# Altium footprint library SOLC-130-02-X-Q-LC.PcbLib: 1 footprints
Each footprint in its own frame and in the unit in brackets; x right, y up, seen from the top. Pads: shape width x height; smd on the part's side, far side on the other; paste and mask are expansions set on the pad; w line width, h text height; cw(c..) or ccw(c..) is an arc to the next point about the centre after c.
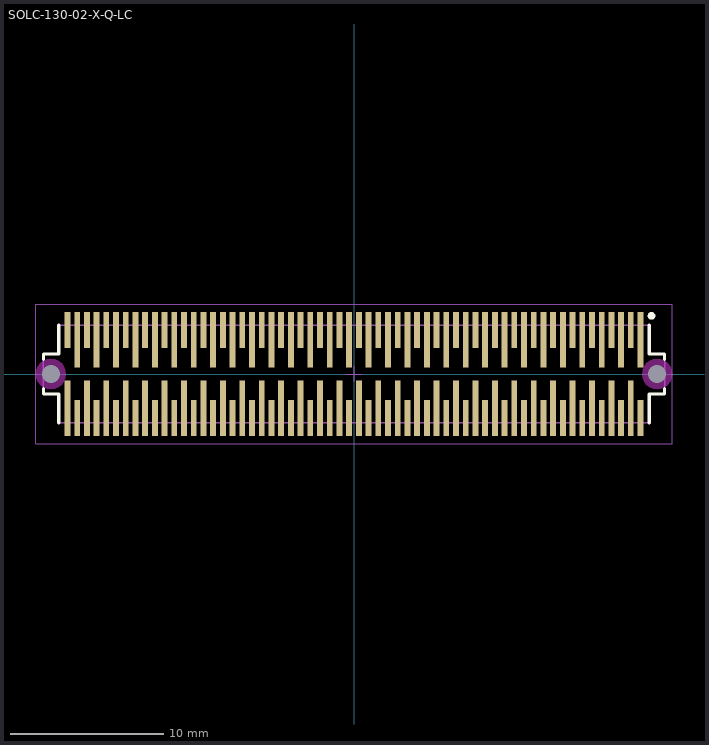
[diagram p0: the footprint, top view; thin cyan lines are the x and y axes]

## SOLC-130-02-X-Q-LC [mm] "1.27mm pitch, 120 pin, socket strip; 4 rows, w/locking clips, SMT"
height 4.62
pads (122):
  rect 0.38x2.36 smd mask+0: A1(18.098,2.885) A2(16.828,2.885) A3(15.557,2.885) A4(14.287,2.885) A5(13.018,2.885) A6(11.747,2.885) A7(10.477,2.885) A8(9.207,2.885) A9(7.938,2.885) A10(6.667,2.885) A11(5.397,2.885) A12(4.127,2.885) A13(2.857,2.885) A14(1.587,2.885) A15(0.318,2.885) A16(-0.953,2.885) A17(-2.222,2.885) A18(-3.492,2.885) A19(-4.763,2.885) A20(-6.032,2.885) A21(-7.302,2.885) A22(-8.572,2.885) A23(-9.842,2.885) A24(-11.112,2.885) A25(-12.383,2.885) A26(-13.652,2.885) A27(-14.922,2.885) A28(-16.192,2.885) A29(-17.462,2.885) A30(-18.732,2.885) D1(18.732,-2.885) D2(17.462,-2.885) D3(16.192,-2.885) D4(14.922,-2.885) D5(13.652,-2.885) D6(12.383,-2.885) D7(11.112,-2.885) D8(9.842,-2.885) D9(8.572,-2.885) D10(7.302,-2.885) D11(6.032,-2.885) D12(4.763,-2.885) D13(3.492,-2.885) D14(2.222,-2.885) D15(0.953,-2.885) D16(-0.318,-2.885) D17(-1.587,-2.885) D18(-2.857,-2.885) D19(-4.127,-2.885) D20(-5.397,-2.885) D21(-6.667,-2.885) D22(-7.938,-2.885) D23(-9.207,-2.885) D24(-10.477,-2.885) D25(-11.747,-2.885) D26(-13.018,-2.885) D27(-14.287,-2.885) D28(-15.557,-2.885) D29(-16.828,-2.885) D30(-18.098,-2.885)
  rect 0.38x3.63 smd mask+0: B1(18.732,2.25) B2(17.462,2.25) B3(16.192,2.25) B4(14.922,2.25) B5(13.652,2.25) B6(12.383,2.25) B7(11.112,2.25) B8(9.842,2.25) B9(8.572,2.25) B10(7.302,2.25) B11(6.032,2.25) B12(4.763,2.25) B13(3.492,2.25) B14(2.222,2.25) B15(0.953,2.25) B16(-0.318,2.25) B17(-1.587,2.25) B18(-2.857,2.25) B19(-4.127,2.25) B20(-5.397,2.25) B21(-6.667,2.25) B22(-7.938,2.25) B23(-9.207,2.25) B24(-10.477,2.25) B25(-11.747,2.25) B26(-13.018,2.25) B27(-14.287,2.25) B28(-15.557,2.25) B29(-16.828,2.25) B30(-18.098,2.25) C1(18.098,-2.25) C2(16.828,-2.25) C3(15.557,-2.25) C4(14.287,-2.25) C5(13.018,-2.25) C6(11.747,-2.25) C7(10.477,-2.25) C8(9.207,-2.25) C9(7.938,-2.25) C10(6.667,-2.25) C11(5.397,-2.25) C12(4.127,-2.25) C13(2.857,-2.25) C14(1.587,-2.25) C15(0.318,-2.25) C16(-0.953,-2.25) C17(-2.222,-2.25) C18(-3.492,-2.25) C19(-4.763,-2.25) C20(-6.032,-2.25) C21(-7.302,-2.25) C22(-8.572,-2.25) C23(-9.842,-2.25) C24(-11.112,-2.25) C25(-12.383,-2.25) C26(-13.652,-2.25) C27(-14.922,-2.25) C28(-16.192,-2.25) C29(-17.462,-2.25) C30(-18.732,-2.25)
  round 1 hole 1.2 unplated mask+0: MTG1(-19.812,0) MTG2(19.812,0)
Top Overlay:
  circle w0.25: c19.45,3.8 r0.125
  lines w0.2: -20.3,-0.95 -20.3,-1.3 -19.3,-1.3 -19.3,-3.2 ; -20.3,0.95 -20.3,1.3 -19.3,1.3 -19.3,3.2 ; 19.3,-3.2 19.3,-1.3 20.3,-1.3 20.3,-0.95 ; 19.3,3.2 19.3,1.3 20.3,1.3 20.3,0.95
Keep-Out Layer:
  pour cut-out: 20.795,0 20.762,0.255 20.664,0.492 20.507,0.695 20.304,0.852 20.067,0.95 19.812,0.983 19.557,0.95 19.32,0.852 19.117,0.695 18.96,0.492 18.862,0.255 18.829,0 18.862,-0.255 18.96,-0.492 19.117,-0.695 19.32,-0.852 19.557,-0.95 19.812,-0.983 20.067,-0.95 20.304,-0.852 20.507,-0.695 20.664,-0.492 20.762,-0.255
  pour cut-out: -18.829,0 -18.862,0.255 -18.96,0.492 -19.117,0.695 -19.32,0.852 -19.557,0.95 -19.812,0.983 -20.067,0.95 -20.304,0.852 -20.507,0.695 -20.664,0.492 -20.762,0.255 -20.795,0 -20.762,-0.255 -20.664,-0.492 -20.507,-0.695 -20.304,-0.852 -20.067,-0.95 -19.812,-0.983 -19.557,-0.95 -19.32,-0.852 -19.117,-0.695 -18.96,-0.492 -18.862,-0.255
Mechanical 12:
  lines w0.001: -20.3,-1.3 -20.3,1.3 -19.3,1.3 -19.3,3.2 19.3,3.2 19.3,1.3 20.3,1.3 20.3,-1.3 19.3,-1.3 19.3,-3.2 -19.3,-3.2 -19.3,-1.3 -20.3,-1.3
Mechanical 13:
  lines w0.1: -20.3,-1.3 -20.3,1.3 -19.3,1.3 -19.3,3.2 19.3,3.2 19.3,1.3 20.3,1.3 20.3,-1.3 19.3,-1.3 19.3,-3.2 -19.3,-3.2 -19.3,-1.3 -20.3,-1.3
  text ".Designator" at 0,-0.127 h1.52
Mechanical 15:
  lines w0.05: -0.5,0 0.5,0 ; 0,-0.5 0,0.5 ; -20.8,-4.55 -20.8,4.55 20.8,4.55 20.8,-4.55 -20.8,-4.55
